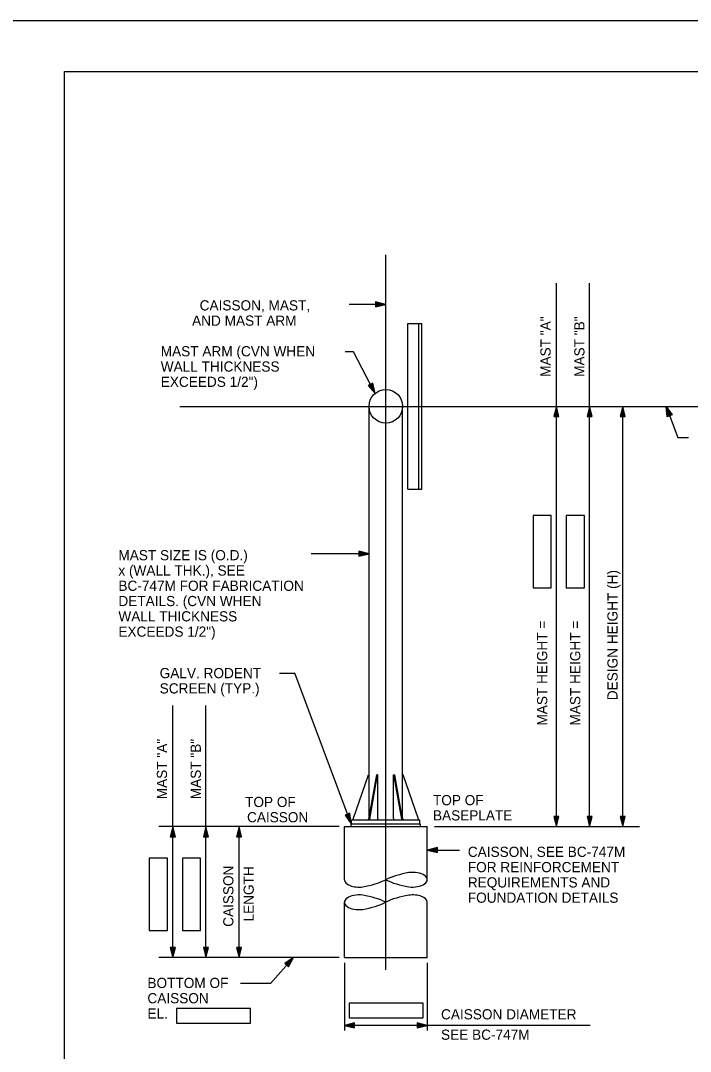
# Model space of a CAD drawing. Extents: x 640117 to 642655, y 297247 to 298435.
# Drawn here: x 640985.6 to 641182.8, y 298132 to 298435.5 of the extents above; entities that cross this region are included whole.
import ezdxf

# ---------------------------------------------------------------- set-up
doc = ezdxf.new("R2010")
doc.units = 0
for name, color, linetype in [('10', 7, 'Continuous'), ('2', 7, 'Continuous'), ('49', 7, 'Continuous'), ('50', 7, 'Continuous'), ('51', 7, 'Continuous'), ('52', 7, 'Continuous'), ('55', 7, 'Continuous'), ('PLT-BNDY', 7, 'Continuous')]:
    doc.layers.add(name, color=color, linetype=linetype)

msp = doc.modelspace()

# ---------------------------------------------------------------- linework, layer by layer
at = {"layer": '10'}
for points in [[(641136.5, 298268.45), (641141.86, 298268.45), (641141.86, 298289.78), (641136.49, 298289.78)], [(641146.25, 298268.45), (641151.62, 298268.45), (641151.62, 298289.78), (641146.25, 298289.78)], [(641023.46, 298167.64), (641028.82, 298167.64), (641028.82, 298188.96), (641023.45, 298188.96)], [(641033.21, 298167.64), (641038.58, 298167.64), (641038.58, 298188.96), (641033.21, 298188.96)]]:
    msp.add_lwpolyline(points, close=True, dxfattribs=at)
at = {"layer": '2'}
for p, q in [((640998.46, 297856.46), (640998.46, 298420.46)), ((640998.46, 298420.46), (641784.46, 298420.46))]:
    msp.add_line(p, q, dxfattribs=at)
for points in [[(641031.48, 298140.39), (641053.23, 298140.39), (641053.23, 298144.64), (641031.48, 298144.64)], [(641082.34, 298141.96), (641104.09, 298141.96), (641104.09, 298146.21), (641082.34, 298146.22)]]:
    msp.add_lwpolyline(points, close=True, dxfattribs=at)
at = {"layer": '49'}
for p, q in [((641099.62, 298297.51), (641099.62, 298346.28)), ((641099.62, 298346.28), (641103.68, 298346.28)), ((641102.87, 298297.51), (641102.87, 298346.28)), ((641103.68, 298297.51), (641103.68, 298346.28)), ((641099.62, 298297.51), (641103.68, 298297.51))]:
    msp.add_line(p, q, dxfattribs=at)
at = {"layer": '50'}
for p, q in [((641093.12, 298156.03), (641093.12, 298366.53)), ((641032.47, 298321.9), (641730.35, 298321.9))]:
    msp.add_line(p, q, dxfattribs=at)
at = {"layer": '51'}
for p, q in [((641080.92, 298198.22), (641105.31, 298198.22)), ((641080.92, 298182.56), (641080.92, 298198.22)), ((641105.31, 298182.56), (641105.31, 298198.22)), ((641080.92, 298159.63), (641080.92, 298175.93)), ((641105.31, 298159.63), (641105.31, 298175.93)), ((641080.92, 298159.63), (641105.31, 298159.63))]:
    msp.add_line(p, q, dxfattribs=at)
for centre, major_axis, start_param, end_param in [((641105.31, 298176.46), (17.24, 0), 1.89032, 2.356194), ((641100.99, 298182.56), (4.32, 0), 4.455588, 8.110783), ((641085.24, 298182.56), (-4.32, 0), 0, 1.827597), ((641080.92, 298188.66), (-17.24, 0), 1.89032, 2.356194), ((641105.31, 298188.66), (17.24, 0), 3.926991, 4.392865), ((641085.24, 298175.93), (-4.32, 0), 4.455588, 8.110783), ((641080.92, 298169.84), (-17.24, 0), 3.926991, 4.392865), ((641105.31, 298169.84), (17.24, 0), 1.89032, 2.356194), ((641100.99, 298175.93), (4.32, 0), 0, 1.827597), ((641080.92, 298182.03), (-17.24, 0), 1.89032, 2.356194)]:
    msp.add_ellipse(centre, major_axis=major_axis, ratio=0.5, start_param=start_param, end_param=end_param, dxfattribs=at)
at = {"layer": '52'}
for p, q in [((641143.36, 298198.22), (641143.36, 298358.17)), ((641153.12, 298198.22), (641153.12, 298358.17)), ((641093.12, 298351.91), (641090.12, 298352.66)), ((641090.12, 298352.66), (641090.12, 298351.16)), ((641090.12, 298351.16), (641093.12, 298351.91)), ((641092.38, 298351.91), (641090.29, 298352.44)), ((641090.29, 298352.44), (641090.29, 298351.39)), ((641090.29, 298351.39), (641092.38, 298351.91)), ((641091.65, 298351.91), (641090.47, 298352.21)), ((641090.47, 298352.21), (641090.47, 298351.62)), ((641090.47, 298351.62), (641091.65, 298351.91)), ((641090.54, 298351.82), (641090.92, 298351.91)), ((641090.92, 298351.91), (641090.56, 298352)), ((641089.28, 298328.75), (641087.95, 298328.05)), ((641087.95, 298328.05), (641090, 298325.74)), ((641089.16, 298328.49), (641088.23, 298328)), ((641088.23, 298328), (641089.66, 298326.39)), ((641089.04, 298328.22), (641088.52, 298327.95)), ((641088.52, 298327.95), (641089.33, 298327.04)), ((641088.73, 298327.98), (641088.99, 298327.69)), ((641088.99, 298327.69), (641088.9, 298328.05)), ((641089.33, 298327.04), (641089.04, 298328.22)), ((641089.66, 298326.39), (641089.16, 298328.49)), ((641090, 298325.74), (641089.28, 298328.75)), ((641143.36, 298321.9), (641142.61, 298318.9)), ((641143.36, 298321.16), (641142.84, 298319.07)), ((641144.11, 298318.9), (641143.36, 298321.9)), ((641143.89, 298319.07), (641143.36, 298321.16)), ((641153.12, 298321.9), (641152.37, 298318.9)), ((641153.12, 298321.16), (641152.59, 298319.07)), ((641153.87, 298318.9), (641153.12, 298321.9)), ((641153.64, 298319.07), (641153.12, 298321.16)), ((641162.87, 298321.9), (641162.12, 298318.9)), ((641162.87, 298321.16), (641162.35, 298319.07)), ((641162.87, 298198.22), (641162.87, 298321.9)), ((641163.62, 298318.9), (641162.87, 298321.9)), ((641163.39, 298319.07), (641162.87, 298321.16)), ((641175.63, 298321.9), (641177.41, 298319.37)), ((641176.01, 298318.83), (641175.63, 298321.9)), ((641175.89, 298321.21), (641177.13, 298319.45)), ((641176.16, 298319.08), (641175.89, 298321.21)), ((641142.61, 298318.9), (641144.11, 298318.9)), ((641142.84, 298319.07), (641143.89, 298319.07)), ((641143.36, 298320.43), (641143.07, 298319.25)), ((641143.07, 298319.25), (641143.66, 298319.25)), ((641143.36, 298319.7), (641143.27, 298319.34)), ((641143.66, 298319.25), (641143.36, 298320.43)), ((641143.46, 298319.32), (641143.36, 298319.7)), ((641152.37, 298318.9), (641153.87, 298318.9)), ((641152.59, 298319.07), (641153.64, 298319.07)), ((641153.12, 298320.43), (641152.82, 298319.25)), ((641152.82, 298319.25), (641153.41, 298319.25)), ((641153.12, 298319.7), (641153.03, 298319.34)), ((641153.41, 298319.25), (641153.12, 298320.43)), ((641153.21, 298319.32), (641153.12, 298319.7)), ((641162.12, 298318.9), (641163.62, 298318.9)), ((641162.35, 298319.07), (641163.39, 298319.07)), ((641162.87, 298320.43), (641162.57, 298319.25)), ((641162.57, 298319.25), (641163.17, 298319.25)), ((641162.87, 298319.7), (641162.78, 298319.34)), ((641163.17, 298319.25), (641162.87, 298320.43)), ((641162.96, 298319.32), (641162.87, 298319.7)), ((641177.41, 298319.37), (641176.01, 298318.83)), ((641176.31, 298319.32), (641176.16, 298320.53)), ((641176.16, 298320.53), (641176.86, 298319.54)), ((641177.13, 298319.45), (641176.16, 298319.08)), ((641176.86, 298319.54), (641176.31, 298319.32)), ((641176.42, 298319.85), (641176.63, 298319.55)), ((641176.47, 298319.46), (641176.42, 298319.85)), ((641088.17, 298278.52), (641085.17, 298279.27)), ((641085.17, 298279.27), (641085.17, 298277.77)), ((641085.17, 298277.77), (641088.17, 298278.52)), ((641087.44, 298278.52), (641085.35, 298279.05)), ((641085.35, 298279.05), (641085.35, 298278)), ((641085.35, 298278), (641087.44, 298278.52)), ((641086.7, 298278.52), (641085.52, 298278.82)), ((641085.52, 298278.82), (641085.52, 298278.23)), ((641085.52, 298278.23), (641086.7, 298278.52)), ((641085.59, 298278.43), (641085.97, 298278.52)), ((641085.97, 298278.52), (641085.61, 298278.61)), ((641082.87, 298199.03), (641066.3, 298243.36)), ((641030.4, 298159.63), (641030.4, 298233.83)), ((641040.15, 298159.63), (641040.15, 298233.83)), ((641082.52, 298202.11), (641081.12, 298201.58)), ((641081.12, 298201.58), (641082.87, 298199.03)), ((641082.37, 298201.86), (641081.39, 298201.49)), ((641081.39, 298201.49), (641082.61, 298199.72)), ((641082.22, 298201.61), (641081.67, 298201.41)), ((641081.67, 298201.41), (641082.36, 298200.41)), ((641081.88, 298201.41), (641082.1, 298201.09)), ((641082.1, 298201.09), (641082.06, 298201.46)), ((641082.36, 298200.41), (641082.22, 298201.61)), ((641082.61, 298199.72), (641082.37, 298201.86)), ((641082.87, 298199.03), (641082.52, 298202.11)), ((641142.61, 298201.22), (641143.36, 298198.22)), ((641144.11, 298201.22), (641142.61, 298201.22)), ((641142.84, 298201.04), (641143.36, 298198.95)), ((641143.89, 298201.04), (641142.84, 298201.04)), ((641143.07, 298200.87), (641143.36, 298199.69)), ((641143.66, 298200.87), (641143.07, 298200.87)), ((641143.27, 298200.79), (641143.36, 298200.42)), ((641143.36, 298198.22), (641144.11, 298201.22)), ((641143.36, 298198.95), (641143.89, 298201.04)), ((641143.36, 298199.69), (641143.66, 298200.87)), ((641143.36, 298200.42), (641143.45, 298200.78)), ((641152.37, 298201.22), (641153.12, 298198.22)), ((641153.87, 298201.22), (641152.37, 298201.22)), ((641152.59, 298201.04), (641153.12, 298198.95)), ((641153.64, 298201.04), (641152.59, 298201.04)), ((641152.82, 298200.87), (641153.12, 298199.69)), ((641153.41, 298200.87), (641152.82, 298200.87)), ((641153.02, 298200.79), (641153.12, 298200.42)), ((641153.12, 298198.22), (641153.87, 298201.22)), ((641153.12, 298198.95), (641153.64, 298201.04)), ((641153.12, 298199.69), (641153.41, 298200.87)), ((641153.12, 298200.42), (641153.21, 298200.78)), ((641162.12, 298201.22), (641162.87, 298198.22)), ((641163.62, 298201.22), (641162.12, 298201.22)), ((641162.35, 298201.04), (641162.87, 298198.95)), ((641163.39, 298201.04), (641162.35, 298201.04)), ((641162.57, 298200.87), (641162.87, 298199.69)), ((641163.17, 298200.87), (641162.57, 298200.87)), ((641162.78, 298200.79), (641162.87, 298200.42)), ((641162.87, 298198.22), (641163.62, 298201.22)), ((641162.87, 298198.95), (641163.39, 298201.04)), ((641162.87, 298199.69), (641163.17, 298200.87)), ((641162.87, 298200.42), (641162.96, 298200.78)), ((641079.42, 298198.22), (641026.31, 298198.22)), ((641030.4, 298198.22), (641029.65, 298195.22)), ((641030.4, 298197.49), (641029.87, 298195.4)), ((641030.4, 298196.75), (641030.1, 298195.58)), ((641031.15, 298195.22), (641030.4, 298198.22)), ((641030.92, 298195.4), (641030.4, 298197.49)), ((641030.69, 298195.58), (641030.4, 298196.75)), ((641040.15, 298198.22), (641039.4, 298195.22)), ((641040.15, 298197.49), (641039.63, 298195.4)), ((641040.15, 298196.75), (641039.85, 298195.58)), ((641040.9, 298195.22), (641040.15, 298198.22)), ((641040.67, 298195.4), (641040.15, 298197.49)), ((641040.45, 298195.58), (641040.15, 298196.75)), ((641049.9, 298198.22), (641049.15, 298195.22)), ((641049.9, 298197.49), (641049.38, 298195.4)), ((641049.9, 298196.75), (641049.61, 298195.58)), ((641049.9, 298159.63), (641049.9, 298198.22)), ((641050.65, 298195.22), (641049.9, 298198.22)), ((641050.43, 298195.4), (641049.9, 298197.49)), ((641050.2, 298195.58), (641049.9, 298196.75)), ((641107.41, 298198.22), (641167.83, 298198.22)), ((641029.65, 298195.22), (641031.15, 298195.22)), ((641029.87, 298195.4), (641030.92, 298195.4)), ((641030.1, 298195.58), (641030.69, 298195.58)), ((641030.4, 298196.02), (641030.31, 298195.66)), ((641030.49, 298195.65), (641030.4, 298196.02)), ((641039.4, 298195.22), (641040.9, 298195.22)), ((641039.63, 298195.4), (641040.67, 298195.4)), ((641039.85, 298195.58), (641040.45, 298195.58)), ((641040.15, 298196.02), (641040.06, 298195.66)), ((641040.24, 298195.65), (641040.15, 298196.02)), ((641049.15, 298195.22), (641050.65, 298195.22)), ((641049.38, 298195.4), (641050.43, 298195.4)), ((641049.61, 298195.58), (641050.2, 298195.58)), ((641049.9, 298196.02), (641049.81, 298195.66)), ((641050, 298195.65), (641049.9, 298196.02)), ((641108.31, 298192.04), (641105.31, 298191.29)), ((641105.31, 298191.29), (641108.31, 298190.55)), ((641108.13, 298191.82), (641106.04, 298191.29)), ((641106.04, 298191.29), (641108.13, 298190.77)), ((641107.95, 298191.59), (641106.77, 298191.29)), ((641106.77, 298191.29), (641107.95, 298191)), ((641107.88, 298191.39), (641107.51, 298191.29)), ((641107.51, 298191.29), (641107.86, 298191.2)), ((641107.95, 298191), (641107.95, 298191.59)), ((641108.13, 298190.77), (641108.13, 298191.82)), ((641108.31, 298190.55), (641108.31, 298192.04)), ((641029.65, 298162.63), (641030.4, 298159.63)), ((641031.15, 298162.63), (641029.65, 298162.63)), ((641029.87, 298162.45), (641030.4, 298160.36)), ((641030.92, 298162.45), (641029.87, 298162.45)), ((641030.1, 298162.27), (641030.4, 298161.09)), ((641030.69, 298162.27), (641030.1, 298162.27)), ((641030.3, 298162.2), (641030.4, 298161.83)), ((641030.4, 298159.63), (641031.15, 298162.63)), ((641030.4, 298160.36), (641030.92, 298162.45)), ((641030.4, 298161.09), (641030.69, 298162.27)), ((641030.4, 298161.83), (641030.49, 298162.18)), ((641039.4, 298162.63), (641040.15, 298159.63)), ((641040.9, 298162.63), (641039.4, 298162.63)), ((641039.63, 298162.45), (641040.15, 298160.36)), ((641040.67, 298162.45), (641039.63, 298162.45)), ((641039.85, 298162.27), (641040.15, 298161.09)), ((641040.45, 298162.27), (641039.85, 298162.27)), ((641040.06, 298162.2), (641040.15, 298161.83)), ((641040.15, 298159.63), (641040.9, 298162.63)), ((641040.15, 298160.36), (641040.67, 298162.45)), ((641040.15, 298161.09), (641040.45, 298162.27)), ((641040.15, 298161.83), (641040.24, 298162.18)), ((641049.15, 298162.63), (641049.9, 298159.63)), ((641050.65, 298162.63), (641049.15, 298162.63)), ((641049.38, 298162.45), (641049.9, 298160.36)), ((641050.43, 298162.45), (641049.38, 298162.45)), ((641049.61, 298162.27), (641049.9, 298161.09)), ((641050.2, 298162.27), (641049.61, 298162.27)), ((641049.81, 298162.2), (641049.9, 298161.83)), ((641049.9, 298159.63), (641050.65, 298162.63)), ((641049.9, 298160.36), (641050.43, 298162.45)), ((641049.9, 298161.09), (641050.2, 298162.27)), ((641049.9, 298161.83), (641049.99, 298162.18)), ((641079.42, 298159.63), (641026.31, 298159.63)), ((641065.91, 298159.63), (641063.35, 298157.88)), ((641063.35, 298157.88), (641064.47, 298156.89)), ((641065.42, 298159.08), (641063.64, 298157.87)), ((641063.64, 298157.87), (641064.42, 298157.17)), ((641064.93, 298158.53), (641063.93, 298157.85)), ((641063.93, 298157.85), (641064.37, 298157.45)), ((641064.45, 298157.98), (641064.14, 298157.78)), ((641064.26, 298157.64), (641064.45, 298157.98)), ((641064.37, 298157.45), (641064.93, 298158.53)), ((641064.42, 298157.17), (641065.42, 298159.08)), ((641064.47, 298156.89), (641065.91, 298159.63)), ((641080.92, 298158.13), (641080.92, 298138.18)), ((641105.31, 298158.13), (641105.31, 298138.18)), ((641083.92, 298140.43), (641080.92, 298139.68)), ((641105.31, 298139.68), (641080.92, 298139.68)), ((641080.92, 298139.68), (641083.92, 298138.93)), ((641083.75, 298140.2), (641081.66, 298139.68)), ((641081.66, 298139.68), (641083.75, 298139.16)), ((641083.57, 298139.98), (641082.39, 298139.68)), ((641082.39, 298139.68), (641083.57, 298139.39)), ((641083.5, 298139.77), (641083.12, 298139.68)), ((641083.12, 298139.68), (641083.48, 298139.59)), ((641083.57, 298139.39), (641083.57, 298139.98)), ((641083.75, 298139.16), (641083.75, 298140.2)), ((641083.92, 298138.93), (641083.92, 298140.43)), ((641105.31, 298139.68), (641102.31, 298140.43)), ((641102.31, 298140.43), (641102.31, 298138.93)), ((641102.31, 298138.93), (641105.31, 298139.68)), ((641104.57, 298139.68), (641102.48, 298140.2)), ((641102.48, 298140.2), (641102.48, 298139.16)), ((641102.48, 298139.16), (641104.57, 298139.68)), ((641103.84, 298139.68), (641102.66, 298139.98)), ((641102.66, 298139.98), (641102.66, 298139.39)), ((641102.66, 298139.39), (641103.84, 298139.68)), ((641102.73, 298139.59), (641103.11, 298139.68)), ((641103.11, 298139.68), (641102.75, 298139.77)), ((641153.34, 298139.68), (641105.31, 298139.68))]:
    msp.add_line(p, q, dxfattribs=at)
for points in [[(641093.12, 298351.91), (641082.29, 298351.91)], [(641090, 298325.74), (641083.63, 298337.94), (641081.17, 298337.94)], [(641175.63, 298321.9), (641179.16, 298312.77), (641182.25, 298312.77)], [(641088.17, 298278.52), (641071.09, 298278.52)], [(641061.81, 298243.36), (641066.3, 298243.36)], [(641105.31, 298191.29), (641114.81, 298191.29)], [(641065.91, 298159.63), (641059.18, 298152.05), (641050.29, 298152.05)]]:
    msp.add_lwpolyline(points, dxfattribs=at)
at = {"layer": '55'}
for p, q in [((641088.17, 298200.2), (641088.17, 298321.9)), ((641098.06, 298200.2), (641098.06, 298321.9)), ((641083.46, 298200.4), (641088.04, 298213.41)), ((641088.24, 298213.41), (641088.04, 298213.41)), ((641088.16, 298200.4), (641090.44, 298213.41)), ((641088.24, 298200.61), (641088.24, 298213.41)), ((641088.24, 298200.2), (641088.24, 298212.09)), ((641088.42, 298200.4), (641090.71, 298213.41)), ((641090.81, 298213.41), (641090.44, 298213.41)), ((641090.81, 298200.61), (641090.81, 298213.41)), ((641095.42, 298200.61), (641095.42, 298213.41)), ((641095.42, 298213.41), (641095.79, 298213.41)), ((641097.81, 298200.4), (641095.52, 298213.41)), ((641098.07, 298200.4), (641095.79, 298213.41)), ((641097.99, 298200.61), (641097.99, 298213.41)), ((641097.99, 298213.41), (641098.19, 298213.41)), ((641097.99, 298200.2), (641097.99, 298212.09)), ((641102.77, 298200.4), (641098.19, 298213.41)), ((641083.06, 298199.03), (641083.06, 298200.2)), ((641083.06, 298200.2), (641103.17, 298200.2)), ((641083.46, 298200.2), (641083.46, 298200.4)), ((641088.24, 298200.61), (641087.83, 298200.2)), ((641088.16, 298200.2), (641088.16, 298200.4)), ((641088.42, 298200.2), (641088.42, 298200.4)), ((641090.81, 298200.61), (641090.61, 298200.2)), ((641095.42, 298200.61), (641095.62, 298200.2)), ((641097.81, 298200.2), (641097.81, 298200.4)), ((641097.99, 298200.61), (641098.4, 298200.2)), ((641098.07, 298200.2), (641098.07, 298200.4)), ((641102.77, 298200.2), (641102.77, 298200.4)), ((641103.17, 298199.03), (641103.17, 298200.2)), ((641082.87, 298198.22), (641082.87, 298199.03)), ((641083.06, 298199.03), (641103.17, 298199.03)), ((641103.36, 298198.22), (641103.36, 298199.03))]:
    msp.add_line(p, q, dxfattribs=at)
msp.add_circle((641093.12, 298321.9), 4.95, dxfattribs=at)
at = {"layer": 'PLT-BNDY'}
msp.add_lwpolyline([(640958.46, 298435.46), (641799.46, 298435.46), (641799.46, 297841.46), (640958.46, 297841.46)], close=True, dxfattribs=at)

# ---------------------------------------------------------------- texts
at = {"layer": '2'}
for s, height, p in [('  CAISSON, MAST,', 3, (641036.07, 298350.14)), ('AND MAST ARM', 3, (641036.07, 298345.64)), ('MAST ARM (CVN WHEN', 3, (641026.84, 298336.63)), ('WALL THICKNESS', 3, (641026.84, 298332.13)), ('EXCEEDS 1/2")', 3, (641026.84, 298327.63)), ('MAST SIZE IS (O.D.)', 3, (641014.37, 298276.6)), ('x (WALL THK.), SEE', 3, (641014.37, 298272.1)), ('BC-747M FOR FABRICATION', 3, (641014.37, 298267.6)), ('DETAILS. (CVN WHEN', 3, (641014.37, 298263.1)), ('WALL THICKNESS', 3, (641014.37, 298258.6)), ('EXCEEDS 1/2")', 3, (641014.37, 298254.1)), ('GALV. RODENT', 3, (641026.53, 298241.89)), ('SCREEN (TYP.)', 3, (641026.53, 298237.39)), ('TOP OF ', 2.992, (641051.69, 298203.96)), ('TOP OF ', 2.995, (641107.01, 298204.5)), ('CAISSON', 2.992, (641052.26, 298199.47)), ('BASEPLATE', 2.995, (641107.01, 298200.01)), ('CAISSON, SEE BC-747M', 3, (641117.27, 298189.28)), ('FOR REINFORCEMENT', 3, (641117.27, 298184.78)), ('REQUIREMENTS AND', 3, (641117.27, 298180.28)), ('FOUNDATION DETAILS', 3, (641117.27, 298175.78)), ('BOTTOM OF', 3, (641022.92, 298150.69)), ('CAISSON', 3, (641022.92, 298146.19)), ('EL.', 3, (641022.92, 298141.69)), ('CAISSON DIAMETER', 3, (641109.38, 298141.45)), ('SEE BC-747M', 3, (641109.38, 298135.45))]:
    msp.add_text(s, height=height, dxfattribs=at).set_placement(p)
for s, height, p in [('MAST "A"', 3, (641141.65, 298330.59)), ('MAST "B"', 3, (641151.62, 298330.59)), ('DESIGN HEIGHT (H)', 3, (641161.37, 298235.4)), ('MAST HEIGHT = ', 3, (641140.65, 298227.94)), ('MAST HEIGHT = ', 3, (641150.4, 298227.94)), ('MAST "A"', 3, (641028.69, 298206.25)), ('MAST "B"', 3, (641038.65, 298206.25)), ('CAISSON', 2.992, (641048.24, 298168.71)), ('LENGTH', 2.992, (641054.23, 298170.27))]:
    msp.add_text(s, height=height, rotation=90, dxfattribs=at).set_placement(p)

doc.saveas('drawing.dxf')
